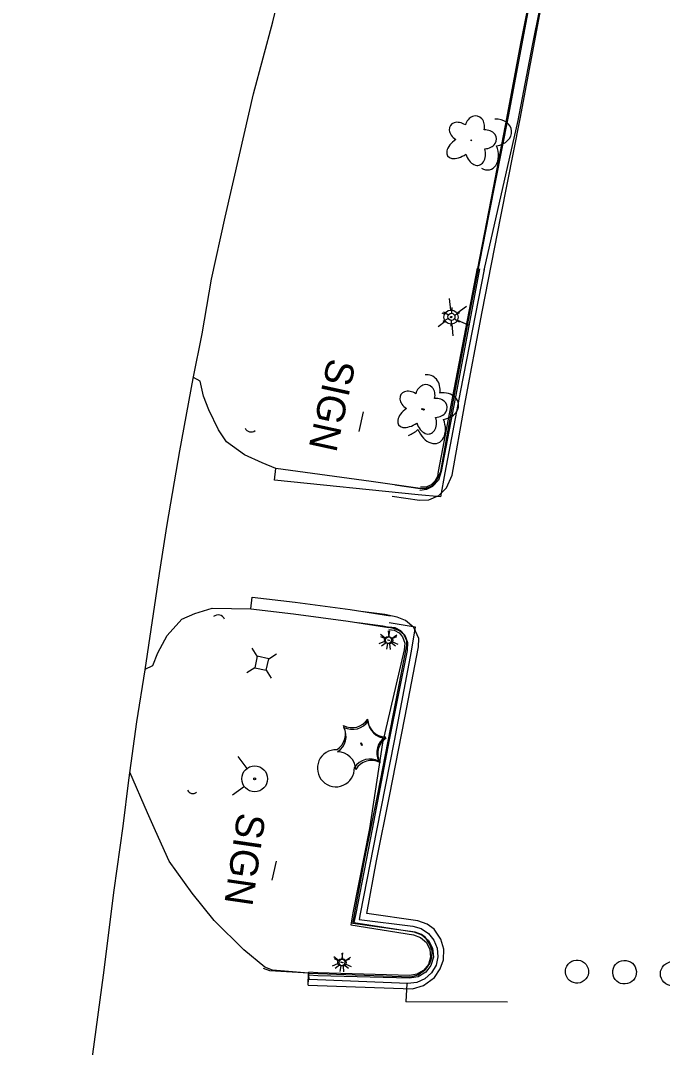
# Model space of a CAD drawing. Extents: x 588843 to 2552415, y 180129 to 269402.
# Drawn here: x 593241.9 to 593378.3, y 185179.7 to 185398.1 of the extents above; entities that cross this region are included whole.
import ezdxf

# ---------------------------------------------------------------- set-up
doc = ezdxf.new("R2010")
doc.units = 0
for name, color, linetype in [('Default', 7, 'Continuous'), ('E_AREA', 7, 'Continuous'), ('E_DRN', 7, 'Continuous'), ('E_DWY', 7, 'Continuous'), ('E_LAND_Vegetation', 7, 'Continuous'), ('E_LTG', 7, 'Continuous'), ('E_RDWY', 7, 'Continuous'), ('E_RDWY_AsphConc', 7, 'Continuous'), ('E_RDWY_C_and_G', 7, 'Continuous'), ('E_SGN', 7, 'Continuous'), ('E_SGN_Text', 7, 'Continuous'), ('E_UTL_AG_Bold', 7, 'Continuous'), ('E_UTL_WHydrant', 7, 'Continuous')]:
    doc.layers.add(name, color=color, linetype=linetype)

# ---------------------------------------------------------------- blocks, each defined once
blk = doc.blocks.new('LPOL')
at = {"layer": 'Default'}
for p, q in [((-4, 0), (-1.5, 0)), ((-0.75, 1.3), (-2, 3.46)), ((0.75, 1.3), (2, 3.46)), ((1.5, 0), (4, 0)), ((-2, -3.46), (-0.75, -1.3)), ((2, -3.46), (0.75, -1.3))]:
    blk.add_line(p, q, dxfattribs=at)
for radius in [1.5, 1.5, 1.5, 0.125]:
    blk.add_circle((0, 0), radius, dxfattribs=at)
blk = doc.blocks.new('SIGN')
at = {"layer": 'Default'}
blk.add_text('SIGN', height=12, dxfattribs=at).set_placement((-18.55, -6))
blk = doc.blocks.new('DTRE')
at = {"layer": 'Default'}
blk.add_circle((-0.18, 0), 0.183, dxfattribs=at)
for centre, major_axis, ratio in [((-1.87, 5.32), (1.36, -4.98), 0.782863), ((4.06, 2.74), (-5.27, -2.93), 0.691916), ((-5.87, 0.15), (4.93, -0.12), 0.832022), ((-2.49, -5.24), (1.8, 4.86), 0.716896), ((3.54, -3.71), (-5.01, 4.58), 0.560249)]:
    blk.add_ellipse(centre, major_axis=major_axis, ratio=ratio, start_param=1.570796, end_param=4.712389, dxfattribs=at)
blk = doc.blocks.new('CULV2')
at = {"layer": 'E_DRN'}
blk.add_arc((19.7, 14.8), 24.6, 216.8699, 323.1301, dxfattribs=at)
blk = doc.blocks.new('PED')
at = {"layer": 'Default'}
for p, q in [((-2.5, 2.5), (-5.33, 5.33)), ((2.5, 2.5), (5.33, 5.33)), ((-2.5, -2.5), (-5.33, -5.33)), ((2.5, -2.5), (5.33, -5.33))]:
    blk.add_line(p, q, dxfattribs=at)
blk.add_lwpolyline([(-2.5, -2.5), (2.5, -2.5), (2.5, 2.5), (-2.5, 2.5)], close=True, dxfattribs=at)
blk = doc.blocks.new('HYD')
at = {"layer": 'Default'}
for p, q in [((-3.84, 3.84), (-8.32, 8.32)), ((3.84, 3.84), (8.32, 8.32))]:
    blk.add_line(p, q, dxfattribs=at)
for radius in [5.48, 0.42]:
    blk.add_circle((0, 0), radius, dxfattribs=at)
blk = doc.blocks.new('CTRE')
at = {"layer": 'Default'}
blk.add_circle((0, 0), 0.223, dxfattribs=at)
for centre, start, end in [((-11.97, 8.96), 280.2067, 5.9716), ((1.81, 14.92), 220.2113, 305.9762), ((13.83, 5.89), 160.2113, 245.9762), ((-13.83, -5.9), 340.2113, 65.9762), ((12.03, -9.04), 185.9272, 100.2511), ((-1.81, -14.93), 40.2113, 125.9762)]:
    blk.add_arc(centre, 7.87, start, end, dxfattribs=at)
blk = doc.blocks.new('LPOL_4')
at = {"layer": 'E_LTG'}
for p, q in [((-13.1, 0), (-4.9, 0)), ((-2.5, 4.3), (-6.6, 11.4)), ((2.5, 4.3), (6.6, 11.4)), ((4.9, 0), (13.1, 0)), ((-6.6, -11.4), (-2.5, -4.3)), ((6.6, -11.4), (2.5, -4.3))]:
    blk.add_line(p, q, dxfattribs=at)
for radius in [4.92, 4.92, 4.92, 0.41]:
    blk.add_circle((0, 0), radius, dxfattribs=at)
blk = doc.blocks.new('CTRE_4')
at = {"layer": 'E_LAND_Vegetation'}
blk.add_circle((0, 0), 0.733, dxfattribs=at)
for centre, start, end in [((-39.3, 29.4), 280.2067, 5.9716), ((5.9, 49), 220.2113, 305.9762), ((45.4, 19.3), 160.2113, 245.9762), ((-45.4, -19.3), 340.2113, 65.9762), ((39.5, -29.6), 100.2511, 185.9272), ((-5.9, -49), 40.2113, 125.9762)]:
    blk.add_arc(centre, 25.8, start, end, dxfattribs=at)

msp = doc.modelspace()

# ---------------------------------------------------------------- linework, layer by layer
at = {"layer": 'E_AREA'}
msp.add_circle((593380.42, 185195.4), 2.55, dxfattribs=at)
for centre, major_axis, ratio in [((593360.15, 185195.86), (-1.92, -1.53), 0.999968), ((593370.25, 185195.73), (-0.16, 2.51), 0.999984)]:
    msp.add_ellipse(centre, major_axis=major_axis, ratio=ratio, dxfattribs=at)
at = {"layer": 'E_DWY'}
for points in [[(593320.88, 185296.96), (593326.69, 185296.11), (593328.7, 185296.16), (593330.81, 185297.08), (593332.43, 185298.77), (593333.62, 185301.46), (593336.23, 185316.14), (593340.01, 185336.19), (593343.97, 185356.46), (593348.07, 185377.21), (593352.45, 185400.61), (593356.32, 185420.99), (593359.89, 185439.49), (593360.7, 185443.74)], [(593321.55, 185299.38), (593326.84, 185298.61), (593328.15, 185298.64), (593329.35, 185299.17), (593330.32, 185300.19), (593331.21, 185302.19), (593333.77, 185316.59), (593337.55, 185336.67), (593341.52, 185356.94), (593345.62, 185377.68), (593349.99, 185401.07), (593351.84, 185410.78)], [(593339.05, 185345.4), (593342.38, 185362.52), (593345.23, 185377.3), (593348.25, 185393.25), (593351.48, 185409.54)], [(593340.44, 185345.06), (593347.68, 185376.83), (593350.7, 185392.77), (593353.93, 185409.07)], [(593295.85, 185300.34), (593296.19, 185302.82), (593293.28, 185304.04), (593289.48, 185305.77), (593285.7, 185308.54), (593284.01, 185311.07), (593281.9, 185315.35), (593280.78, 185318.21), (593280.07, 185321.4), (593278.66, 185322.22)], [(593326.86, 185298.59), (593316.39, 185300.09), (593296.19, 185302.82)], [(593326.42, 185297.25), (593295.85, 185300.34)], [(593268.43, 185260.15), (593270.06, 185260.93), (593271.1, 185263.68), (593273.09, 185267.33), (593276.18, 185270.8), (593278.96, 185272.01), (593282.63, 185273.15), (593290.84, 185273), (593291.13, 185275.49)], [(593291.13, 185275.49), (593300.24, 185274.42), (593311.93, 185272.84), (593320.53, 185271.48)], [(593290.84, 185273), (593299.93, 185271.94), (593311.56, 185270.37), (593320.16, 185269.01)], [(593303.07, 185192.99), (593325.2, 185192.2), (593327.53, 185192.9), (593329.87, 185194.58), (593331.1, 185196.42), (593331.81, 185198.38), (593331.87, 185200.6), (593331.19, 185202.72), (593329.78, 185204.85), (593328.34, 185205.94), (593326.34, 185206.65), (593315.47, 185208.21), (593317.55, 185219.44), (593320.31, 185233.14), (593323.57, 185249.82), (593326.49, 185264.95), (593326.54, 185266.7), (593325.48, 185269.01), (593323.74, 185270.51), (593321.93, 185271.22), (593319.35, 185271.78), (593314.21, 185272.44)], [(593303.16, 185195.49), (593324.88, 185194.71), (593326.41, 185195.17), (593328.04, 185196.34), (593328.86, 185197.56), (593329.32, 185198.85), (593329.36, 185200.24), (593328.91, 185201.62), (593327.93, 185203.11), (593327.13, 185203.72), (593325.74, 185204.22), (593312.54, 185206.11), (593315.1, 185219.91), (593317.86, 185233.62), (593321.12, 185250.3), (593324, 185265.22), (593324.02, 185266.19), (593323.43, 185267.47), (593322.43, 185268.34), (593321.2, 185268.82), (593318.92, 185269.32), (593313.58, 185270)], [(593303.03, 185193.05), (593303.12, 185195.54), (593295.43, 185196.14), (593293.8, 185196.83), (593289.34, 185200.5), (593283.07, 185206.71), (593278.42, 185212.5), (593273.51, 185219.33), (593270.62, 185225.82), (593268.9, 185229.64), (593265.16, 185238.27)], [(593303.07, 185192.99), (593303.16, 185195.49), (593294.87, 185196.05), (593293.57, 185196.53)]]:
    msp.add_lwpolyline(points, dxfattribs=at)
at = {"layer": 'E_LAND_Vegetation'}
msp.add_circle((593327.56, 185315.4), 0.128, dxfattribs=at)
for centre, major_axis, ratio, start_param, end_param in [((593342.67, 185374.28), (-3.58, -0.5), 0.782863, 1.570796, 4.600135), ((593340.35, 185370.4), (-1.56, 3.92), 0.691916, 2.455165, 4.712389), ((593328.18, 185319.34), (-0.53, -3.41), 0.832022, 1.570796, 3.43567), ((593331.4, 185316.1), (-3.58, -0.5), 0.782863, 1.570796, 4.712389), ((593329.08, 185312.21), (-1.56, 3.92), 0.691916, 1.570796, 4.712389), ((593324.65, 185313.15), (3.63, 3.07), 0.560249, 4.204374, 4.712389)]:
    msp.add_ellipse(centre, major_axis=major_axis, ratio=ratio, start_param=start_param, end_param=end_param, dxfattribs=at)
at = {"layer": 'E_LTG'}
for p, q in [((593333, 185339.01), (593333.24, 185336.53)), ((593334.61, 185335.91), (593336.64, 185337.36)), ((593330.67, 185333.08), (593332.17, 185334.16)), ((593331.44, 185335.92), (593332.02, 185335.65)), ((593334.76, 185334.41), (593337.03, 185333.38)), ((593333.54, 185333.54), (593333.78, 185331.05))]:
    msp.add_line(p, q, dxfattribs=at)
for radius in [1.5, 0.125]:
    msp.add_circle((593333.39, 185335.03), radius, dxfattribs=at)
at = {"layer": 'E_RDWY'}
for points in [[(593282.48, 185343.12), (593285.41, 185356.31), (593288.47, 185369.55), (593291.42, 185382.49), (593295.56, 185397.86), (593299.32, 185413.37), (593304.07, 185430.15), (593305.83, 185435.64), (593311.64, 185457.14), (593316.6, 185472.82), (593321.43, 185487.25), (593327.9, 185506.35), (593333.84, 185524.27), (593339.47, 185539.74), (593344.26, 185551.86), (593348.77, 185563.29), (593354.98, 185579.26), (593359.35, 185589.84), (593364.2, 185600.61), (593369.48, 185612.01), (593375.46, 185621.77), (593380.94, 185631.55)], [(593241.94, 185042.69), (593242.07, 185044.43), (593243.46, 185057.46), (593244.75, 185070.98), (593246.92, 185092.4), (593248.71, 185108.2), (593250.63, 185125), (593252.09, 185137.47), (593253.87, 185152.57), (593255.5, 185164.44), (593257.32, 185178.27), (593259.58, 185195.12), (593261.85, 185213.17), (593263.77, 185226.77), (593264.92, 185236.57), (593266.67, 185248.98), (593268.41, 185260.06), (593271.46, 185280.49), (593273.1, 185290.92), (593275.78, 185306.6), (593278.62, 185322.02), (593280.53, 185331.47), (593282.48, 185343.12)]]:
    msp.add_lwpolyline(points, dxfattribs=at)
at = {"layer": 'E_RDWY_AsphConc'}
for points in [[(593324, 185193.32), (593323.82, 185189.46)], [(593345.37, 185189.35), (593323.82, 185189.46)]]:
    msp.add_lwpolyline(points, dxfattribs=at)
at = {"layer": 'E_RDWY_C_and_G'}
for points in [[(593340.44, 185345.14), (593335.42, 185319.41), (593332.09, 185301.91), (593331.15, 185296.82), (593326.42, 185297.25)], [(593339.46, 185345.33), (593334.62, 185319.58), (593331.27, 185302.18), (593330.72, 185300.4), (593329.48, 185299.01), (593329.48, 185299.01), (593328.21, 185298.36), (593326.79, 185298.15), (593326.79, 185298.15)], [(593338.92, 185345.42), (593333.96, 185319.62), (593330.63, 185302.2), (593330.48, 185301.12), (593329.98, 185300.15), (593329.19, 185299.39), (593329.19, 185299.39), (593328.1, 185298.91), (593326.9, 185298.86), (593326.9, 185298.86)], [(593320.27, 185270.1), (593325.8, 185269.21), (593324.94, 185263.99), (593321.33, 185244.93), (593317.56, 185225.87), (593314.07, 185208.13), (593313.9, 185206.96), (593325.28, 185205.49), (593327.05, 185204.99), (593328.59, 185203.98), (593329.75, 185202.56), (593330.45, 185200.86), (593330.61, 185199.03), (593330.61, 185199.03), (593330.2, 185197.19), (593329.24, 185195.56), (593327.84, 185194.3), (593326.12, 185193.52), (593324.24, 185193.31), (593324.24, 185193.31), (593305.02, 185194.11), (593303.28, 185194.2), (593303.17, 185195.13), (593303.15, 185195.73)], [(593320.18, 185268.61), (593321.32, 185268.45), (593322.34, 185267.91), (593323.11, 185267.05), (593323.11, 185267.05), (593323.58, 185265.69), (593323.43, 185264.26), (593323.43, 185264.26), (593318.8, 185244.54), (593316.07, 185226.27), (593312.51, 185208.33), (593312.12, 185205.8), (593325.38, 185203.69), (593326.92, 185203.13), (593328.15, 185202.04), (593328.89, 185200.57), (593329.03, 185198.93), (593329.03, 185198.93), (593328.57, 185197.38), (593327.57, 185196.1), (593326.17, 185195.28), (593324.57, 185195.02), (593324.57, 185195.02), (593305.07, 185195.59), (593303.15, 185195.73)], [(593320.15, 185269.19), (593321.46, 185269), (593322.63, 185268.39), (593323.54, 185267.43), (593323.54, 185267.43), (593324.15, 185265.85), (593324.04, 185264.17), (593324.04, 185264.17), (593320.25, 185245.17), (593316.62, 185226.14), (593313.16, 185208.23), (593312.72, 185206.31), (593325.46, 185204.31), (593327.21, 185203.69), (593328.61, 185202.46), (593329.46, 185200.81), (593329.64, 185198.96), (593329.64, 185198.96), (593329.13, 185197.18), (593328, 185195.71), (593326.41, 185194.76), (593324.58, 185194.46), (593324.58, 185194.46), (593305.06, 185194.92), (593303.17, 185195.13)]]:
    msp.add_lwpolyline(points, dxfattribs=at)
at = {"layer": 'E_SGN'}
for points in [[(593313.88, 185310.75), (593314.81, 185314.87)], [(593295.38, 185215.31), (593296.31, 185219.37)]]:
    msp.add_lwpolyline(points, dxfattribs=at)

# ---------------------------------------------------------------- block references
at = {"layer": 'E_DRN'}
for p, xscale, yscale, rotation in [((593289.66, 185311.45), 0.05534296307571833, 0.05534296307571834, -14.219704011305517), ((593285.28, 185270.82), 0.06087313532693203, 0.06087313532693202, 167.01007019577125), ((593277.39, 185234.44), 0.05058388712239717, 0.050583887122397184, -12.205105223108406)]:
    msp.add_blockref('CULV2', p, dxfattribs=dict(at, xscale=xscale, yscale=yscale, rotation=rotation))
at = {"layer": 'E_LAND_Vegetation'}
for name, p, xscale, yscale, rotation in [('DTRE', (593337.68, 185372.55), 0.49999999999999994, 0.5000000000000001, -103.13319961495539), ('DTRE', (593327.21, 185315.4), 0.5, 0.5, -102.33242894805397), ('CTRE', (593314.28, 185244.39), 0.5, 0.5, -98.33108331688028), ('CTRE_4', (593314.46, 185244.06), 0.1524003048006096, 0.1524003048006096, -97.36026881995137)]:
    msp.add_blockref(name, p, dxfattribs=dict(at, xscale=xscale, yscale=yscale, rotation=rotation))
at = {"layer": 'E_LTG'}
for name, p, xscale, yscale, rotation in [('LPOL', (593333.48, 185335.1), 0.5000000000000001, 0.5, -92.95824964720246), ('LPOL', (593320, 185266.37), 0.5, 0.5, -98.33108331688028), ('LPOL_4', (593320.24, 185266.31), 0.1524003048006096, 0.15240030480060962, -84.36014555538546), ('LPOL', (593310.06, 185197.84), 0.5, 0.5, -98.33108331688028), ('LPOL_4', (593310.37, 185197.78), 0.1524003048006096, 0.15240030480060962, -84.36014555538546)]:
    msp.add_blockref(name, p, dxfattribs=dict(at, xscale=xscale, yscale=yscale, rotation=rotation))
at = {"layer": 'E_SGN_Text', "xscale": 0.5, "yscale": 0.5}
for p, rotation in [((593308.26, 185316.81), -102.33242894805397), ((593289.69, 185220.23), -98.33108331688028)]:
    msp.add_blockref('SIGN', p, dxfattribs=dict(at, rotation=rotation))
at = {"layer": 'E_UTL_AG_Bold', "xscale": 0.5, "yscale": 0.5, "rotation": -102.33242894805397}
msp.add_blockref('PED', (593293.17, 185261.43), dxfattribs=at)
at = {"layer": 'E_UTL_WHydrant', "xscale": 0.5, "yscale": 0.5000000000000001, "rotation": 81.406779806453}
msp.add_blockref('HYD', (593291.67, 185236.85), dxfattribs=at)

doc.saveas('drawing.dxf')
